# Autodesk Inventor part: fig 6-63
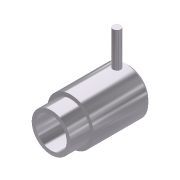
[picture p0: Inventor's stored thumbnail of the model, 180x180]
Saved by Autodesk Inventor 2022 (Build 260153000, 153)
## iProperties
Created: 2001-12
Part Number: fig 6-63
Document SubType Name: Modeling
Designer: Renu Muthoo
Density: 1 g/cm^3
Material: Generic
Appearance: Metal-AL-6061 (Polished)
Control State: 0
Master: False
Checked Out: False
Shininess: 77.0
Angle Display Precision: 2
Document Length Units: 11269
Document Angle Units: 11279
Document Time Units: 11290
Document Mass Units: 11283
Document Length Units Precision: 3
Document Angle Units Precision: 2
Compacted: True
Density: 0.0
Volumn: 0.0
Area: 0.0
PropertySet Name: Model Information
Author: Renu Muthoo
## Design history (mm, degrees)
sketch "Sketch2"
  geometry: L1 (-9.573, -4.327)-(-9.573, -5.327); L2 (-9.573, -5.327)-(-4.573, -5.327); L3 (-4.573, -5.327)-(-4.573, -6.327); L4 (-4.573, -6.327)-(9.427, -6.327); L5 (9.427, -6.327)-(10.427, -5.327); L6 (10.427, -5.327)-(10.427, -4.327); L7 (10.427, -4.327)-(-9.573, -4.327); L8 (-13.687, -0.327)-(14, -0.327)
  constraints: 16 end point, 5 parallel, 1 perpendicular, 1 vertical
  dimensions: "d9" = 20 distance of L6.end L1.start; "d10" = 5 distance of L1.end L2.end; "d11" = 12 diameter of L4 L8; "d12" = 10 diameter of L2 L8; "d13" = 8 diameter of L7 L8; "d14" = 45 deg angle of L5 L4; "d15" = 1 horizontal distance of L5.end L4.end
revolve "Revolution2" sketch "Sketch2" stored, may be unused: angle "d16" = 90 deg
workplane "Work Plane1"
workplane "Work Plane2"
sketch "Sketch3"
  geometry: L1 (-4, 8)-(4, 8) reference; C1 r 1 at (-0.098, 5)
  constraints: 1 centre point
  dimensions: "d18" = 3 distance from line of L1 C1.centre; "d19" = 2 diameter of C1
extrude "Extrusion1" join sketch "Sketch3" distance "d20" = 10; taper "d21" = 0 deg
body "Solid1"
other parameters: "d17" = -1
